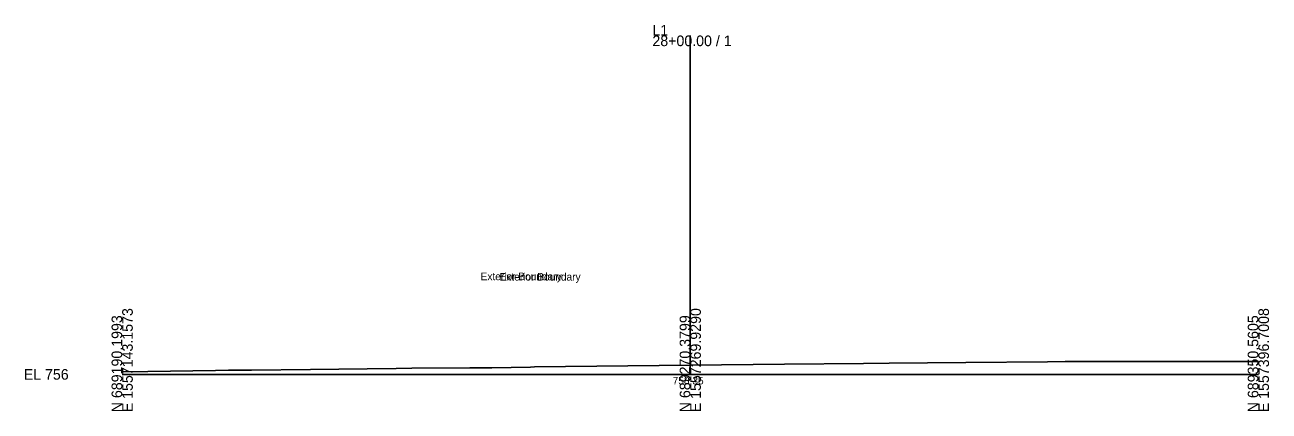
# Model space of a CAD drawing. Extents: x -26 to 2603, y -3010 to 9589.
# Drawn here: x 974.3 to 1302.8, y 1490.3 to 1592.2 of the extents above; entities that cross this region are included whole.
import ezdxf

# ---------------------------------------------------------------- set-up
doc = ezdxf.new("R2010")
doc.units = 0
for name, color, linetype in [('Default', 7, 'Continuous'), ('Exist Cross Section Cell', 7, 'Continuous'), ('Exist XS Center Line Elevation Label', 7, 'Continuous'), ('Exist XS Ground Line', 7, 'Continuous')]:
    doc.layers.add(name, color=color, linetype=linetype)

msp = doc.modelspace()

# ---------------------------------------------------------------- linework, layer by layer
at = {"layer": 'Exist Cross Section Cell'}
for p, q in [((1150, 1500), (1150, 1589.44)), ((1000, 1500), (1150, 1500)), ((1150, 1500), (1300, 1500))]:
    msp.add_line(p, q, dxfattribs=at)
at = {"layer": 'Exist XS Ground Line'}
msp.add_lwpolyline([(1000, 1500.7), (1006.74, 1500.76), (1024.65, 1501.02), (1028.08, 1501.07), (1034.12, 1501.15), (1049.75, 1501.33), (1064.7, 1501.44), (1072.32, 1501.53), (1076.48, 1501.6), (1091.8, 1501.76), (1097.57, 1501.76), (1107.85, 1501.94), (1108.89, 1501.95), (1150, 1502.4), (1174.84, 1502.67), (1195.73, 1502.91), (1202.55, 1503), (1222.8, 1503.16), (1244.34, 1503.33), (1249.02, 1503.37), (1256.75, 1503.44), (1274.73, 1503.41), (1288.85, 1503.4), (1297.15, 1503.39), (1300, 1503.4)], dxfattribs=at)

# ---------------------------------------------------------------- texts
at = {"layer": 'Default'}
for s, height, p in [('Exterior Boundary', 2, (1094.64, 1524.86)), ('Exterior Boundary', 2, (1099.64, 1524.76)), ('-', 0.0001, (1000, 1500))]:
    msp.add_text(s, height=height, dxfattribs=at).set_placement(p)
at = {"layer": 'Exist Cross Section Cell'}
for s, p in [('L1', (1140, 1589.44)), ('28+00.00 / 1', (1140, 1586.64)), ('EL 756', (974, 1498.6))]:
    msp.add_text(s, height=2.8, dxfattribs=at).set_placement(p)
for s, p in [('N 689190.1993', (1000, 1490)), ('E 1557143.1573', (1002.8, 1490)), ('N 689270.3799', (1150, 1490)), ('E 1557269.9290', (1152.8, 1490)), ('N 689350.5605', (1300, 1490)), ('E 1557396.7008', (1302.8, 1490))]:
    msp.add_text(s, height=2.8, rotation=90, dxfattribs=at).set_placement(p)
at = {"layer": 'Exist XS Center Line Elevation Label'}
msp.add_text('758.35', height=2, dxfattribs=at).set_placement((1145.35, 1497.35))

doc.saveas('drawing.dxf')
